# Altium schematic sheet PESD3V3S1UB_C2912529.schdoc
size 127 x 101 mm
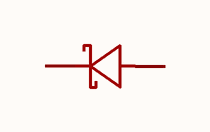
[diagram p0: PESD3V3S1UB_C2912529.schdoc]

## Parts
D?  pesd3v3s1ub_c2912529  [SOD-523_L1.2-W0.8-LS1.6-RD]  (value not drawn)

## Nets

Not connected (* = marked no-connect by the designer): D? 1(K) 2(A)

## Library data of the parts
D? = pesd3v3s1ub_c2912529: PESD3V3S1UB  5V 单向 静电放电(ESD)保护器件; Manufacturer: TECH PUBLIC(台舟); AddInBom: yes; ModelId: 8f56a03db567494d8f4c9d12aa52a741; ModelName: SOD-523_L1.2-W0.8-H0.7-LS1.6; ModelTransform: 62.992,31.496,0,180,0,0,0,0,0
